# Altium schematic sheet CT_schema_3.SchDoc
size 276 x 169 mm
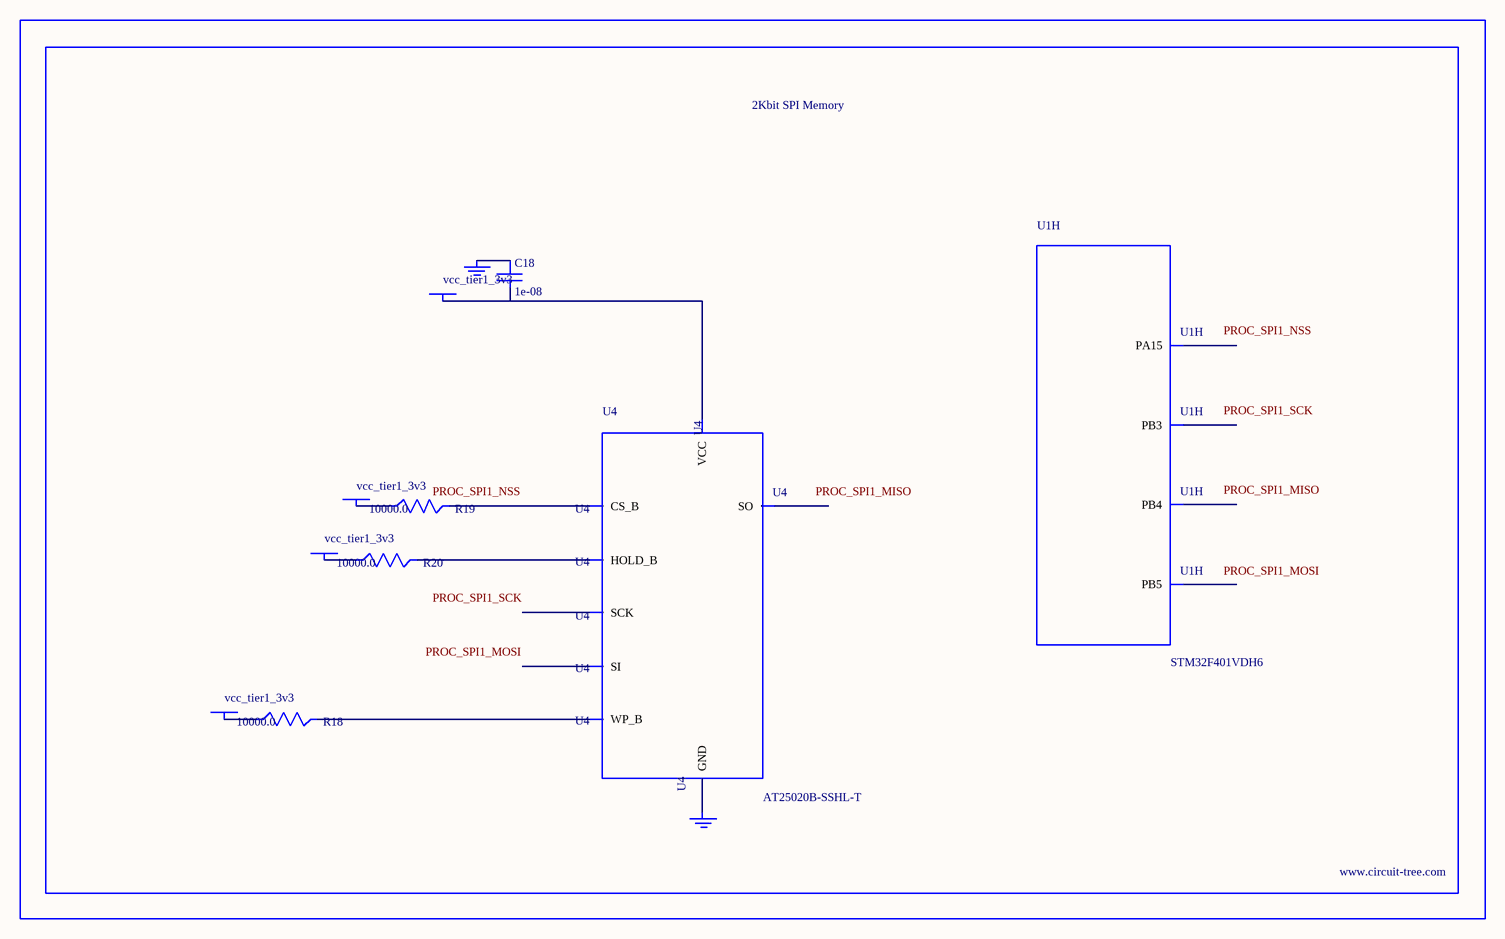
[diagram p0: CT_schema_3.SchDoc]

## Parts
BORDER2  (no value)
C18  1e-08  [C0402]
GND_INSTANCE_2_0  (no value)
GND_INSTANCE_2_1  (no value)
POWER_INSTANCE_2_0  vcc_tier1_3v3
POWER_INSTANCE_2_1  vcc_tier1_3v3
POWER_INSTANCE_2_2  vcc_tier1_3v3
POWER_INSTANCE_2_3  vcc_tier1_3v3
R18  10000.0  [R0603]
R19  10000.0  [R0603]
R20  10000.0  [R0603]
U1  STM32F401VDH6  [UFBGA100]  (part H of 10)
U4  AT25020B-SSHL-T  [SOIC-8]

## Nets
NetC18_1: C18.1 GND_INSTANCE_2_0.0(GND)
NetC18_2: C18.2 POWER_INSTANCE_2_3.0(PWR) U4.8(VCC)
NetGND_INSTANCE_2_1_0: GND_INSTANCE_2_1.0(GND) U4.4(GND)
NetPOWER_INSTANCE_2_0_0: POWER_INSTANCE_2_0.0(PWR) R19.1
NetPOWER_INSTANCE_2_1_0: POWER_INSTANCE_2_1.0(PWR) R18.1
NetPOWER_INSTANCE_2_2_0: POWER_INSTANCE_2_2.0(PWR) R20.1
NetR18_2: R18.2 U4.3(WP_B)
NetR19_2: R19.2 U4.1(CS_B)
NetR20_2: R20.2 U4.7(HOLD_B)

Not connected (* = marked no-connect by the designer): U1 A7(PB4) A8(PB3) A9(PA15) C5(PB5); U4 2(SO) 5(SI) 6(SCK)

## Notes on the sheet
- Labels drawn without touching a wire or pin: PROC_SPI1_MISO, PROC_SPI1_MOSI, PROC_SPI1_NSS, PROC_SPI1_SCK

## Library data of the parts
BORDER2 = BORDER_PAGE2
C18 = C0402C103K3RAC
GND_INSTANCE_2_0 GND_INSTANCE_2_1 = GND
POWER_INSTANCE_2_0-POWER_INSTANCE_2_3 = PWR
R18-R20 = RC0603JR-0710KL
